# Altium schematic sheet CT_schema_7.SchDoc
size 412 x 333 mm
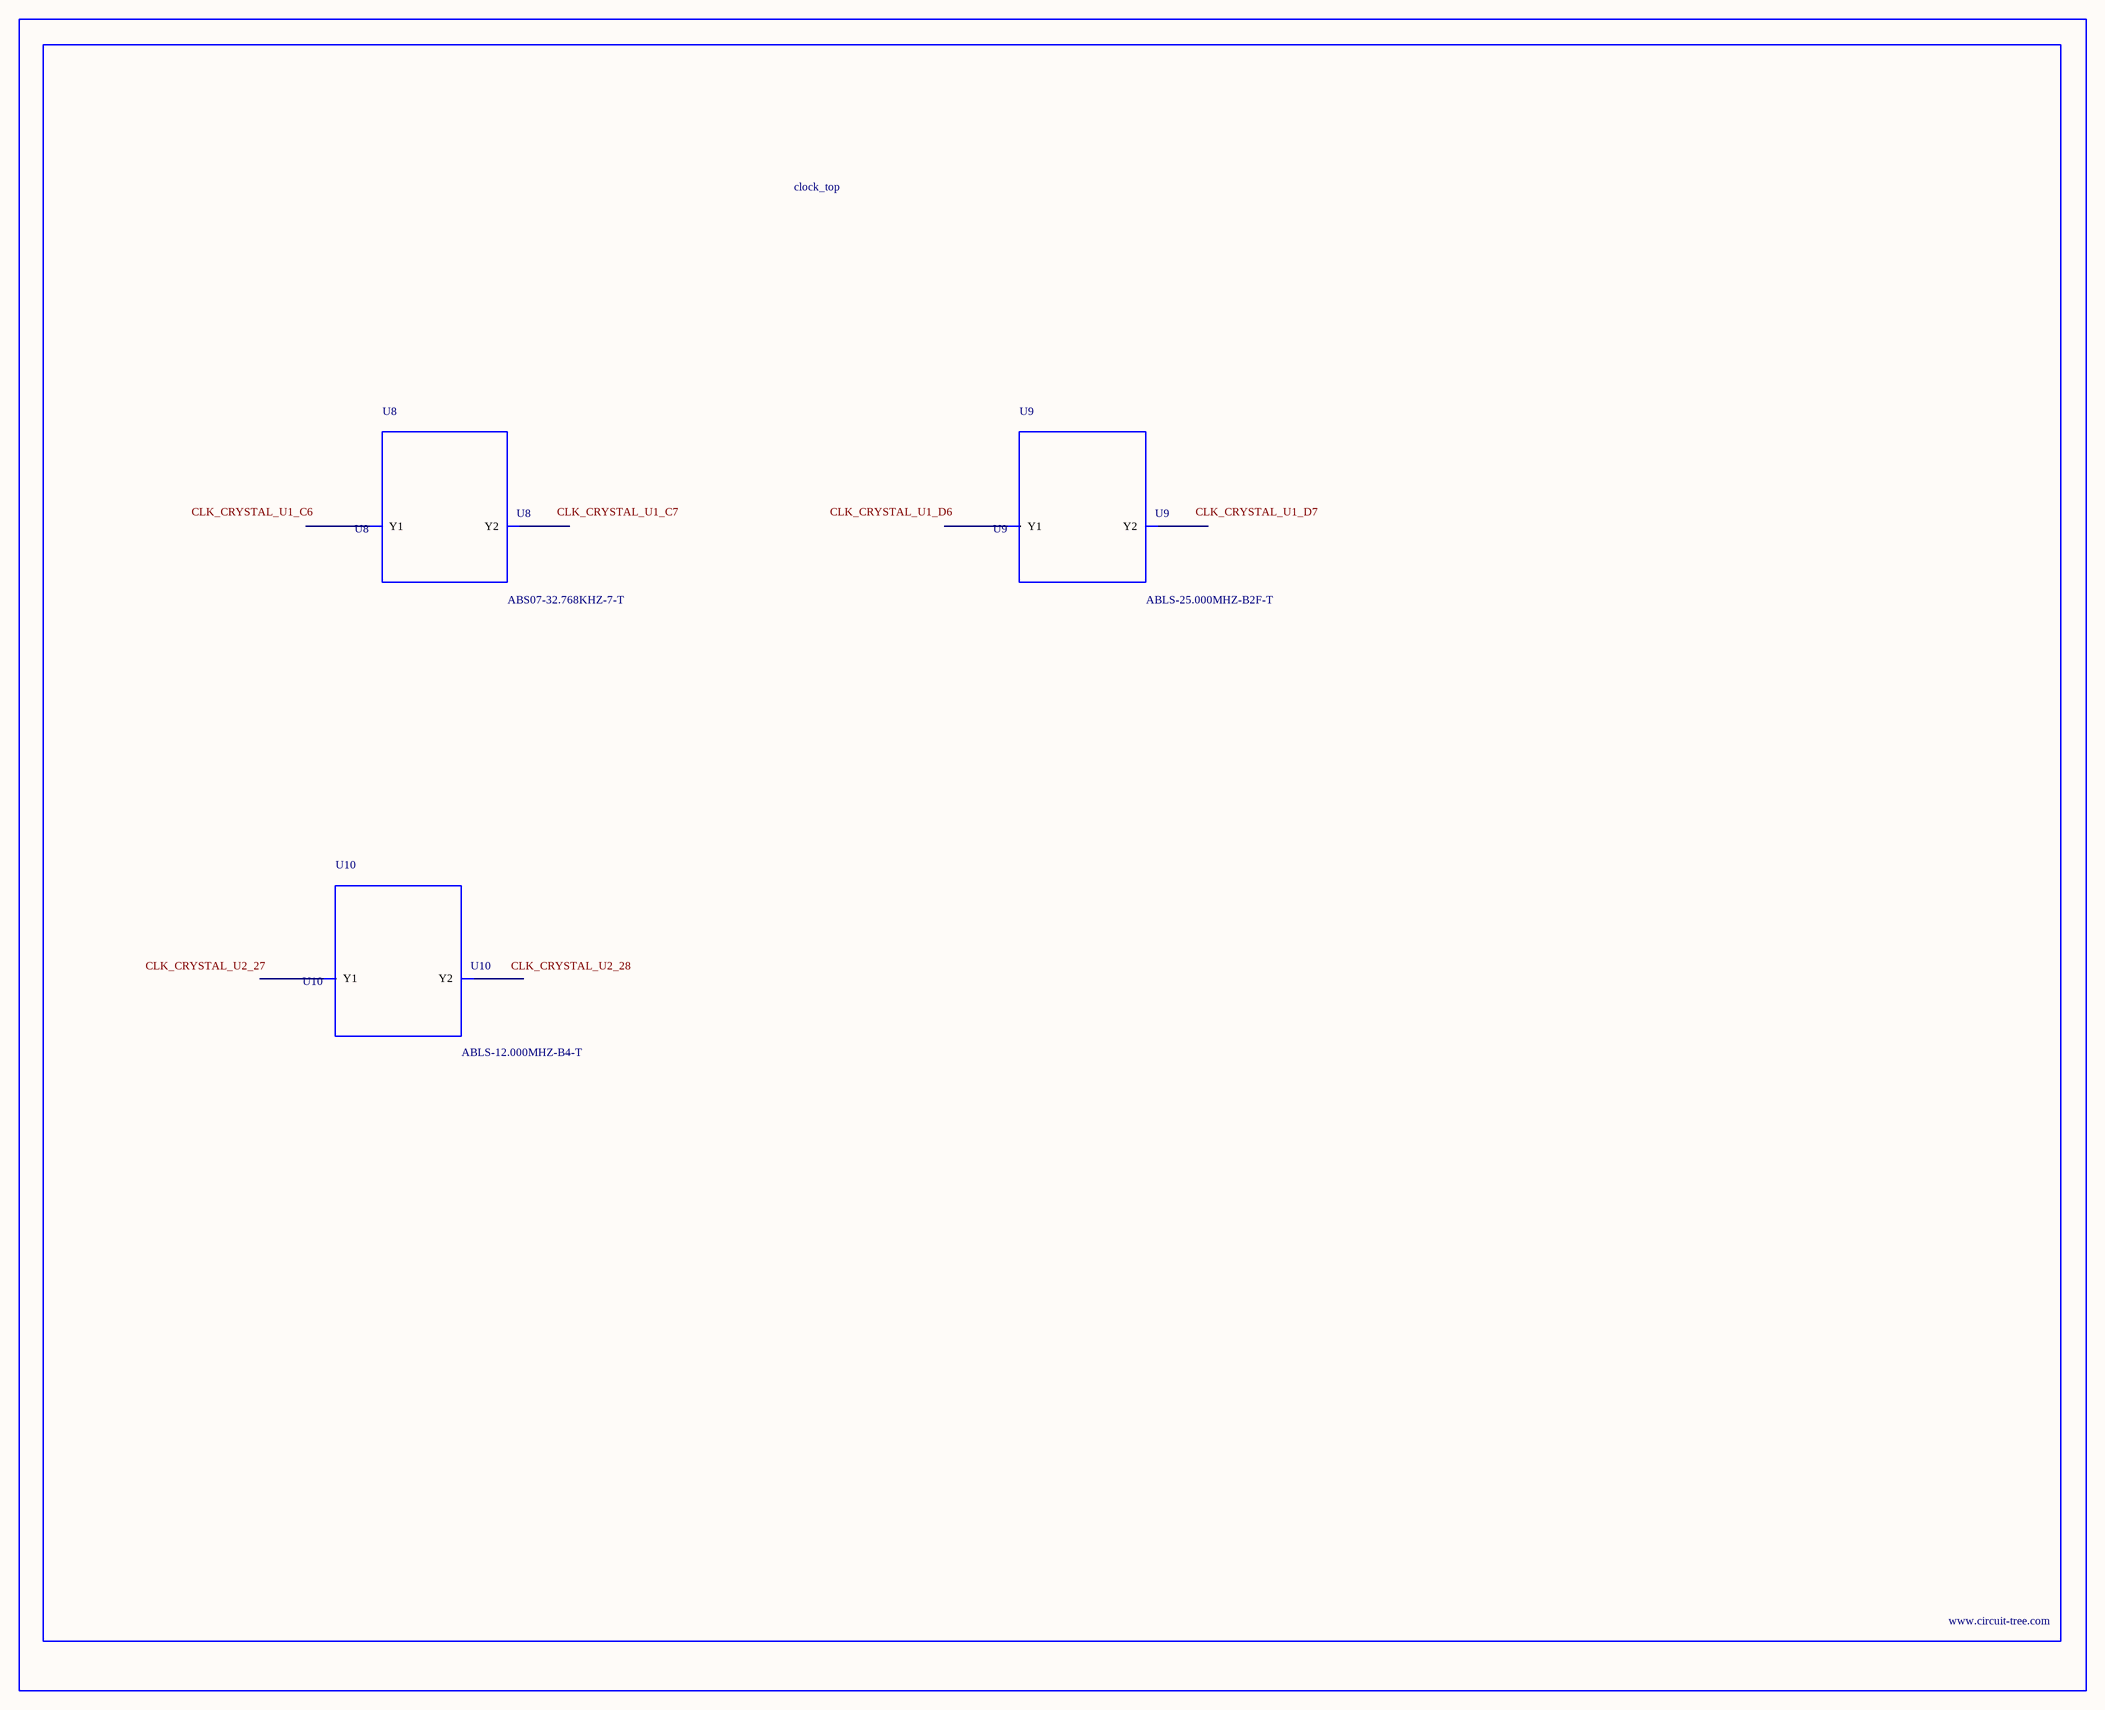
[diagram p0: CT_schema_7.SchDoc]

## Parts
BORDER6  (no value)
U8  ABS07-32.768KHZ-7-T  [ABS07-32.768KHZ-7-T]
U9  ABLS-25.000MHZ-B2F-T  [ABLS-25.000MHZ-B2F-T]
U10  ABLS-12.000MHZ-B4-T  [ABLS-12.000MHZ-B4-T]

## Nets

Not connected (* = marked no-connect by the designer): U8 1(Y1) 2(Y2); U9 1(Y1) 2(Y2); U10 1(Y1) 2(Y2)

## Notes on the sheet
- Labels drawn without touching a wire or pin: CLK_CRYSTAL_U1_C6, CLK_CRYSTAL_U1_C7, CLK_CRYSTAL_U1_D6, CLK_CRYSTAL_U1_D7, CLK_CRYSTAL_U2_27, CLK_CRYSTAL_U2_28

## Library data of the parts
BORDER6 = BORDER_PAGE6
